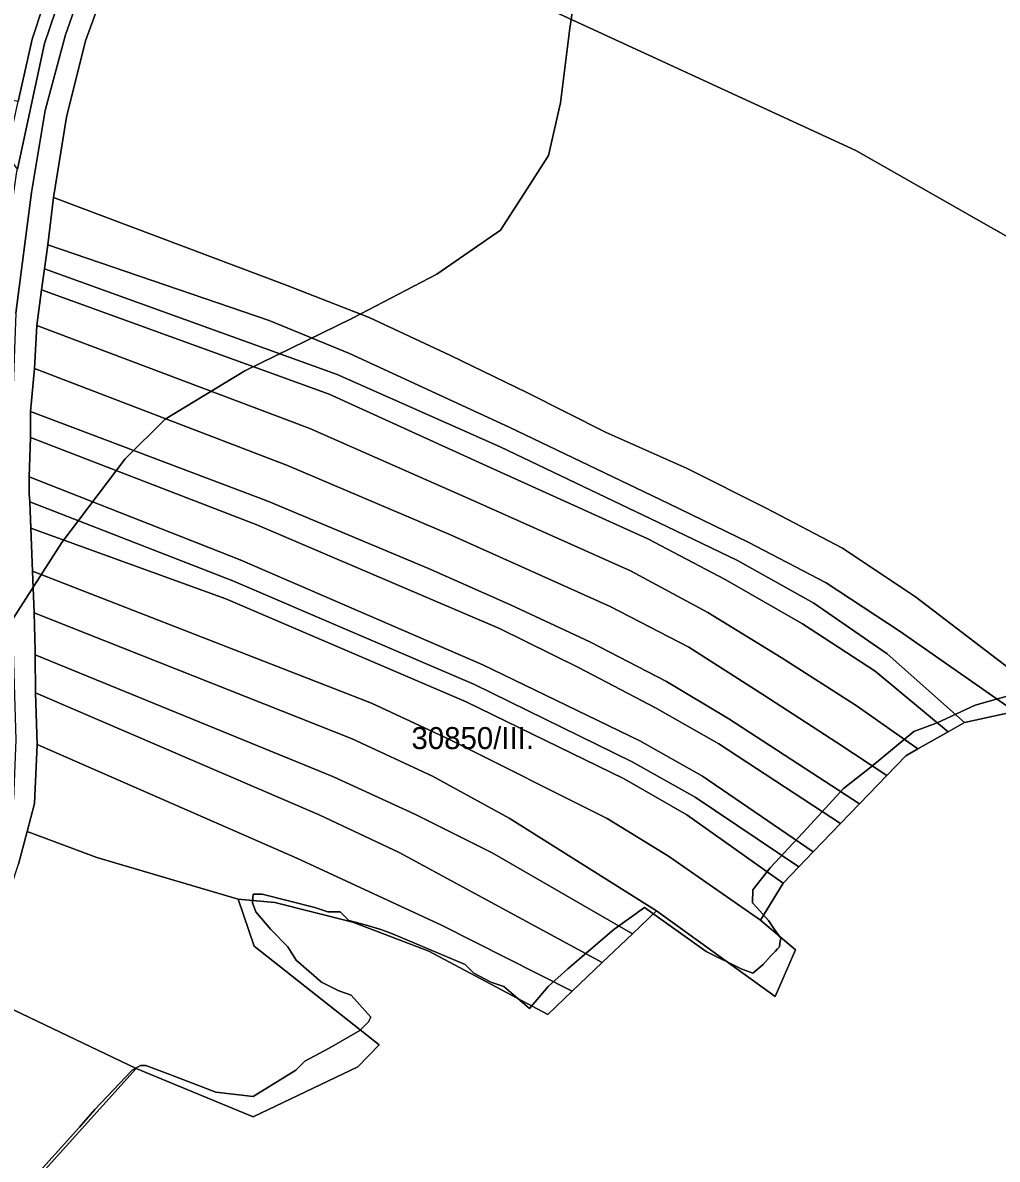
# Model space of a CAD drawing. Extents: x -541351 to -537540, y -1162694 to -1159725.
# Drawn here: x -538206.8 to -537985.1, y -1161953.3 to -1161694.8 of the extents above; entities that cross this region are included whole.
import ezdxf

# ---------------------------------------------------------------- set-up
doc = ezdxf.new("R2010")
doc.units = 0
for name, color, linetype in [('95560013', 7, 'Continuous'), ('95590013', 7, 'Continuous'), ('95600013', 7, 'Continuous'), ('95610013', 7, 'Continuous'), ('95620013', 7, 'Continuous'), ('95640013', 7, 'Continuous'), ('95660013', 7, 'Continuous')]:
    doc.layers.add(name, color=color, linetype=linetype)

msp = doc.modelspace()

# ---------------------------------------------------------------- linework, layer by layer
at = {"layer": '95560013'}
msp.add_lwpolyline([(-538171.84, -1161653.01), (-538140.69, -1161594.04), (-538033.98, -1161648.19), (-537927.26, -1161702.34), (-537935.04, -1161722.01), (-537934.61, -1161724.27), (-537922.75, -1161786.65), (-537976.1, -1161747.28), (-538017.3, -1161723.84), (-538107.66, -1161682.18)], close=True, dxfattribs=at)
msp.add_lwpolyline([(-537972.84, -1161848.95), (-538003.7, -1161825.37), (-538020.32, -1161814.34), (-538037.67, -1161805.21), (-538055.69, -1161796.19), (-538074.06, -1161787.96), (-538091.99, -1161778.95), (-538109.61, -1161770.43), (-538127.98, -1161761.85), (-538146.62, -1161754.58), (-538199.78, -1161734.53), (-538196.85, -1161716.26), (-538192.49, -1161698.9), (-538186.37, -1161682.08), (-538180.3, -1161669.35), (-538178.66, -1161665.92), (-538171.84, -1161653.01), (-538107.66, -1161682.18), (-538017.3, -1161723.84), (-537976.1, -1161747.28)], dxfattribs=at)
at = {"layer": '95590013'}
for points in [[(-538091.99, -1161778.95), (-538074.06, -1161787.96), (-538055.69, -1161796.19), (-538037.67, -1161805.21), (-538020.32, -1161814.34), (-538003.7, -1161825.37), (-537972.84, -1161848.95), (-537973.7, -1161849.78), (-537981.13, -1161851.43), (-538007.24, -1161833.28), (-538024.07, -1161822.21), (-538041.78, -1161812.94), (-538059.87, -1161804.11), (-538096.14, -1161786.78), (-538132.5, -1161770.02), (-538150.71, -1161762.54), (-538201.11, -1161745.28), (-538199.78, -1161734.53), (-538146.62, -1161754.58), (-538127.98, -1161761.85), (-538109.61, -1161770.43)], [(-538026.82, -1161826.8), (-538044.18, -1161817.14), (-538062.2, -1161808.5), (-538098.22, -1161791.29), (-538135.28, -1161774.83), (-538201.84, -1161750.78), (-538201.11, -1161745.28), (-538150.71, -1161762.54), (-538132.5, -1161770.02), (-538096.14, -1161786.78), (-538059.87, -1161804.11), (-538041.78, -1161812.94), (-538024.07, -1161822.21), (-538007.24, -1161833.28), (-537981.13, -1161851.43), (-537992.56, -1161853.98), (-538010.17, -1161838.34)]]:
    msp.add_lwpolyline(points, close=True, dxfattribs=at)
at = {"layer": '95600013'}
msp.add_lwpolyline([(-538199.62, -1161683.33), (-538204.63, -1161698.55), (-538207.8, -1161712.71), (-538211.55, -1161711.92), (-538212.27, -1161705.46), (-538214.18, -1161698.78), (-538215.47, -1161696.4), (-538220.27, -1161691.93)], dxfattribs=at)
for points in [[(-538098.22, -1161791.29), (-538062.2, -1161808.5), (-538044.18, -1161817.14), (-538026.82, -1161826.8), (-538010.17, -1161838.34), (-537992.56, -1161853.98), (-537996.3, -1161856.09), (-538012.86, -1161842.29), (-538029.46, -1161831.54), (-538047.03, -1161821.43), (-538064.61, -1161812.16), (-538101.32, -1161795.56), (-538137.09, -1161779.26), (-538202.56, -1161755.54), (-538201.84, -1161750.78), (-538135.28, -1161774.83)], [(-538203.6, -1161763.66), (-538202.56, -1161755.54), (-538137.09, -1161779.26), (-538101.32, -1161795.56), (-538064.61, -1161812.16), (-538047.03, -1161821.43), (-538029.46, -1161831.54), (-538012.86, -1161842.29), (-537996.3, -1161856.09), (-538003.18, -1161859.97), (-538017.21, -1161850.12), (-538034.31, -1161839.15), (-538050.99, -1161828.92), (-538068.57, -1161819.47), (-538104.86, -1161803.2), (-538141.47, -1161787.07)], [(-538204.12, -1161773.43), (-538203.6, -1161763.66), (-538141.47, -1161787.07), (-538104.86, -1161803.2), (-538068.57, -1161819.47), (-538050.99, -1161828.92), (-538034.31, -1161839.15), (-538017.21, -1161850.12), (-538003.18, -1161859.97), (-538005.94, -1161861.52), (-538010.24, -1161865.99), (-538021.62, -1161858.48), (-538038.44, -1161847.61), (-538055.26, -1161836.82), (-538073.18, -1161827.6), (-538109.47, -1161811.24), (-538146.55, -1161795.5)], [(-538055.26, -1161836.82), (-538038.44, -1161847.61), (-538021.62, -1161858.48), (-538010.24, -1161865.99), (-538016.49, -1161872.48), (-538046.2, -1161853.15), (-538060.38, -1161844.63), (-538077.81, -1161835.61), (-538095.86, -1161827.19), (-538114.48, -1161818.96), (-538151.08, -1161803.59), (-538205.03, -1161783.21), (-538204.12, -1161773.43), (-538146.55, -1161795.5), (-538109.47, -1161811.24), (-538073.18, -1161827.6)], [(-538080.36, -1161841.47), (-538098.31, -1161832.58), (-538153.52, -1161808.99), (-538205.04, -1161789.17), (-538205.03, -1161783.21), (-538151.08, -1161803.59), (-538114.48, -1161818.96), (-538095.86, -1161827.19), (-538077.81, -1161835.61), (-538060.38, -1161844.63), (-538046.2, -1161853.15), (-538016.49, -1161872.48), (-538020.76, -1161876.92), (-538048.47, -1161858.82), (-538062.88, -1161850.64)], [(-538080.36, -1161841.47), (-538062.88, -1161850.64), (-538048.47, -1161858.82), (-538020.76, -1161876.92), (-538026.97, -1161883.38), (-538052.14, -1161866.18), (-538066.41, -1161858.14), (-538102.17, -1161840.8), (-538157.36, -1161816.97), (-538205.3, -1161798.05), (-538205.04, -1161789.17), (-538153.52, -1161808.99), (-538098.31, -1161832.58)], [(-538205.18, -1161803.76), (-538205.3, -1161801.86), (-538205.3, -1161798.05), (-538157.36, -1161816.97), (-538102.17, -1161840.8), (-538066.41, -1161858.14), (-538052.14, -1161866.18), (-538026.97, -1161883.38), (-538030.27, -1161886.81), (-538053.82, -1161870.94), (-538068.19, -1161862.9), (-538104.07, -1161845.34), (-538159.02, -1161821.74)], [(-538204.93, -1161809.73), (-538205.18, -1161803.76), (-538159.02, -1161821.74), (-538104.07, -1161845.34), (-538068.19, -1161862.9), (-538053.82, -1161870.94), (-538030.27, -1161886.81), (-538033.84, -1161890.51), (-538055.73, -1161874.94), (-538070, -1161866.8), (-538105.95, -1161849.29), (-538160.62, -1161825.86)], [(-538055.73, -1161874.94), (-538033.84, -1161890.51), (-538038.96, -1161898.93), (-538059.87, -1161884.33), (-538073.85, -1161875.82), (-538109.89, -1161857.72), (-538127.47, -1161849.58), (-538204.57, -1161819.51), (-538204.93, -1161809.73), (-538160.62, -1161825.86), (-538105.95, -1161849.29), (-538070, -1161866.8)], [(-538131.86, -1161857.65), (-538204.21, -1161829.02), (-538204.57, -1161819.51), (-538127.47, -1161849.58), (-538109.89, -1161857.72), (-538073.85, -1161875.82), (-538059.87, -1161884.33), (-538038.96, -1161898.93), (-538031.03, -1161905.68), (-538035.67, -1161916.29), (-538062.65, -1161896.78), (-538096.14, -1161875.71), (-538113.62, -1161866.16)], [(-538100.02, -1161883.56), (-538117.59, -1161874.77), (-538136.07, -1161866.3), (-538203.96, -1161838.54), (-538203.97, -1161837.63), (-538204.21, -1161829.02), (-538131.86, -1161857.65), (-538113.62, -1161866.16), (-538096.14, -1161875.71), (-538062.65, -1161896.78), (-538068.12, -1161902.01)], [(-538068.12, -1161902.01), (-538074.96, -1161908.56), (-538121.19, -1161883.5), (-538139.39, -1161874.97), (-538203.86, -1161847.18), (-538203.96, -1161838.54), (-538136.07, -1161866.3), (-538117.59, -1161874.77), (-538100.02, -1161883.56)], [(-538203.86, -1161847.18), (-538139.39, -1161874.97), (-538121.19, -1161883.5), (-538074.96, -1161908.56), (-538081.8, -1161915.09), (-538111.51, -1161900.07), (-538144.45, -1161884.8), (-538203.5, -1161858.98)], [(-538157.77, -1161894.11), (-538189.93, -1161884.64), (-538205.8, -1161878.72), (-538204.12, -1161872.38), (-538203.5, -1161858.98), (-538144.45, -1161884.8), (-538111.51, -1161900.07), (-538081.8, -1161915.09), (-538087.35, -1161920.4), (-538114.45, -1161905.95), (-538131.71, -1161899.38), (-538149.46, -1161894.92)], [(-538154.17, -1161904.79), (-538125.74, -1161927.28), (-538130.55, -1161932.26), (-538154.41, -1161943.61), (-538181.01, -1161932.67), (-538217.39, -1161915.26), (-538207.73, -1161886.21), (-538205.8, -1161878.72), (-538189.93, -1161884.64), (-538157.77, -1161894.11)]]:
    msp.add_lwpolyline(points, close=True, dxfattribs=at)
at = {"layer": '95610013'}
msp.add_lwpolyline([(-538224.69, -1161936.84), (-538219.04, -1161919.65), (-538217.39, -1161915.26), (-538181.01, -1161932.67), (-538241.75, -1162000), (-538274.52, -1162040.2), (-538289.23, -1162051.98), (-538284.85, -1162037.35), (-538264.1, -1161997.03)], close=True, dxfattribs=at)
at = {"layer": '95620013'}
msp.add_lwpolyline([(-538241.75, -1162000), (-538181.01, -1161932.67), (-538154.41, -1161943.61), (-538130.55, -1161932.26), (-538125.74, -1161927.28), (-538154.17, -1161904.79), (-538157.77, -1161894.11), (-538149.46, -1161894.92), (-538131.71, -1161899.38), (-538114.45, -1161905.95), (-538087.35, -1161920.4), (-538081.8, -1161915.09), (-538074.96, -1161908.56), (-538068.12, -1161902.01), (-538062.65, -1161896.78), (-538035.67, -1161916.29), (-538031.03, -1161905.68), (-538038.96, -1161898.93), (-538033.84, -1161890.51), (-538030.27, -1161886.81), (-538026.97, -1161883.38), (-538020.76, -1161876.92), (-538016.49, -1161872.48), (-538010.24, -1161865.99), (-538005.94, -1161861.52), (-538003.18, -1161859.97), (-537996.3, -1161856.09), (-537992.56, -1161853.98), (-537981.13, -1161851.43)], dxfattribs=at)
at = {"layer": '95640013'}
for points in [[(-538210.11, -1161723), (-538207.8, -1161712.71), (-538204.63, -1161698.55), (-538199.62, -1161683.33), (-538198.66, -1161680.43), (-538185.41, -1161668.8), (-538190.95, -1161680.06), (-538195.61, -1161681.18), (-538201.83, -1161699.49), (-538208.02, -1161728.1), (-538211.22, -1161723.71)], [(-538204.78, -1161733.41), (-538208.38, -1161760.87), (-538209.13, -1161781.4), (-538210.23, -1161802.12), (-538209, -1161837.65), (-538208.38, -1161857.93), (-538208.88, -1161871.32), (-538210.46, -1161876.94), (-538211, -1161872.06), (-538211.32, -1161869.1), (-538213.07, -1161855.72), (-538216.03, -1161834.89), (-538213.8, -1161777.08), (-538210.63, -1161749.26), (-538210.16, -1161744.89), (-538209.4, -1161737.76), (-538208.14, -1161728.64), (-538208.02, -1161728.1), (-538201.83, -1161699.49), (-538195.61, -1161681.18), (-538190.95, -1161680.06), (-538197.05, -1161697.53), (-538201.67, -1161714.79)]]:
    msp.add_lwpolyline(points, close=True, dxfattribs=at)
for points in [[(-538208.38, -1161760.87), (-538204.78, -1161733.41), (-538201.67, -1161714.79), (-538197.05, -1161697.53), (-538190.95, -1161680.06)], [(-538186.37, -1161682.08), (-538192.49, -1161698.9), (-538196.85, -1161716.26), (-538199.78, -1161734.53), (-538201.11, -1161745.28), (-538201.84, -1161750.78), (-538202.56, -1161755.54), (-538203.6, -1161763.66), (-538204.12, -1161773.43), (-538205.03, -1161783.21), (-538205.04, -1161789.17), (-538205.3, -1161798.05), (-538205.3, -1161801.86), (-538205.18, -1161803.76), (-538204.93, -1161809.73), (-538204.57, -1161819.51), (-538204.21, -1161829.02), (-538203.97, -1161837.63), (-538203.96, -1161838.54), (-538203.86, -1161847.18), (-538203.5, -1161858.98), (-538204.12, -1161872.38), (-538205.8, -1161878.72), (-538207.73, -1161886.21)]]:
    msp.add_lwpolyline(points, dxfattribs=at)
at = {"layer": '95660013'}
for points in [[(-538294.1, -1161966.67), (-538292.69, -1161952), (-538285.29, -1161943.07), (-538276.12, -1161932), (-538260.12, -1161915), (-538244.62, -1161889), (-538224.87, -1161855), (-538197.87, -1161813), (-538183.5, -1161794), (-538174.37, -1161785), (-538156.31, -1161774), (-538131.81, -1161762), (-538112.62, -1161752), (-538098.12, -1161742), (-538092.05, -1161732.56), (-538087.19, -1161725), (-538084.5, -1161713), (-538082.37, -1161696), (-538080.81, -1161686)], [(-538080.81, -1161686), (-538082.37, -1161696), (-538084.5, -1161713), (-538087.19, -1161725), (-538092.05, -1161732.56), (-538098.12, -1161742), (-538112.62, -1161752), (-538131.81, -1161762), (-538156.31, -1161774), (-538174.37, -1161785), (-538183.5, -1161794), (-538197.87, -1161813), (-538224.87, -1161855)], [(-537975.87, -1161846), (-537990.12, -1161850), (-537998.81, -1161854), (-538004.12, -1161856), (-538013.81, -1161864), (-538020.12, -1161869), (-538028.37, -1161878), (-538036.81, -1161887), (-538040.69, -1161892), (-538040.81, -1161895), (-538039.81, -1161896), (-538037.19, -1161899), (-538035.94, -1161900.78), (-538034.37, -1161903), (-538034.55, -1161904.11), (-538034.69, -1161905), (-538035.1, -1161905.44), (-538035.62, -1161906), (-538036.62, -1161907), (-538038.37, -1161909), (-538040.69, -1161911), (-538043.37, -1161910), (-538051.31, -1161906), (-538065.37, -1161896), (-538072.37, -1161901), (-538082.81, -1161910), (-538087.31, -1161914), (-538091.5, -1161919), (-538097.37, -1161914), (-538100.31, -1161913), (-538104.19, -1161911), (-538106.19, -1161909), (-538122.69, -1161902), (-538125.31, -1161901), (-538128.87, -1161900), (-538132.62, -1161899), (-538134.62, -1161897), (-538137.37, -1161897), (-538140.37, -1161896), (-538152.37, -1161893), (-538154.37, -1161893), (-538154.5, -1161895), (-538153.81, -1161897), (-538150.37, -1161901), (-538146.5, -1161905), (-538144.62, -1161908), (-538138.81, -1161913), (-538134.87, -1161915), (-538132.12, -1161916), (-538127.62, -1161921), (-538128.12, -1161922), (-538130.12, -1161924), (-538137.12, -1161928), (-538142.62, -1161931), (-538144.69, -1161933), (-538154.37, -1161939), (-538162.87, -1161938), (-538173.37, -1161934), (-538178.81, -1161932), (-538180, -1161932), (-538181.87, -1161933), (-538190.37, -1161942), (-538193.87, -1161946), (-538205.62, -1161959)], [(-538205.62, -1161959), (-538193.87, -1161946), (-538190.37, -1161942), (-538181.87, -1161933), (-538180, -1161932), (-538178.81, -1161932), (-538173.37, -1161934), (-538162.87, -1161938), (-538154.37, -1161939), (-538144.69, -1161933), (-538142.62, -1161931), (-538137.12, -1161928), (-538130.12, -1161924), (-538128.12, -1161922), (-538127.62, -1161921), (-538132.12, -1161916), (-538134.87, -1161915), (-538138.81, -1161913), (-538144.62, -1161908), (-538146.5, -1161905), (-538150.37, -1161901), (-538153.81, -1161897), (-538154.5, -1161895), (-538154.37, -1161893), (-538152.37, -1161893), (-538140.37, -1161896), (-538137.37, -1161897), (-538134.62, -1161897), (-538132.62, -1161899), (-538128.87, -1161900), (-538125.31, -1161901), (-538122.69, -1161902), (-538106.19, -1161909), (-538104.19, -1161911), (-538100.31, -1161913), (-538097.37, -1161914), (-538091.5, -1161919), (-538087.31, -1161914), (-538082.81, -1161910), (-538072.37, -1161901), (-538065.37, -1161896), (-538051.31, -1161906), (-538043.37, -1161910), (-538040.69, -1161911), (-538038.37, -1161909), (-538036.62, -1161907), (-538035.62, -1161906), (-538035.1, -1161905.44), (-538034.69, -1161905), (-538034.55, -1161904.11), (-538034.37, -1161903), (-538035.94, -1161900.78), (-538037.19, -1161899), (-538039.81, -1161896), (-538040.81, -1161895), (-538040.69, -1161892), (-538036.81, -1161887), (-538028.37, -1161878), (-538020.12, -1161869), (-538013.81, -1161864), (-538004.12, -1161856), (-537998.81, -1161854), (-537990.12, -1161850), (-537975.87, -1161846)]]:
    msp.add_lwpolyline(points, dxfattribs=at)

# ---------------------------------------------------------------- texts
msp.add_text('30850/III.', height=5, rotation=0, dxfattribs=at).set_placement((-538118.37, -1161860))

doc.saveas('drawing.dxf')
